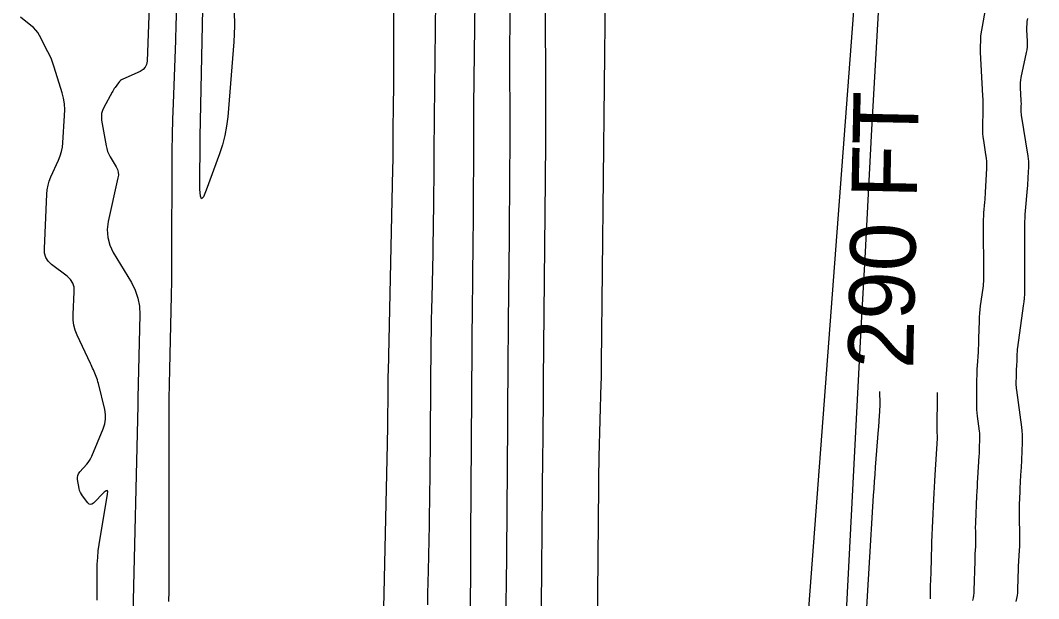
# Model space of a CAD drawing. Extents: x 1768942 to 1774819, y 723037 to 732099.
# Drawn here: x 1770462.7 to 1770556.2, y 730327.7 to 730380.8 of the extents above; entities that cross this region are included whole.
import ezdxf

# ---------------------------------------------------------------- set-up
doc = ezdxf.new("R2010")
doc.units = 0
for name, color, linetype in [('R_Contour Annot', 7, 'Continuous'), ('R_Contours', 7, 'Continuous'), ('R_Horz Alg', 7, 'Continuous')]:
    doc.layers.add(name, color=color, linetype=linetype)

msp = doc.modelspace()

# ---------------------------------------------------------------- linework, layer by layer
at = {"layer": 'R_Contours'}
for points in [[(1770503.977, 730319.774), (1770504.052, 730330.497), (1770504.054, 730330.74), (1770504.056, 730330.984), (1770504.058, 730331.227), (1770504.06, 730331.47), (1770504.07, 730332.443), (1770504.072, 730332.687), (1770504.074, 730332.93), (1770504.076, 730333.173), (1770504.078, 730333.417), (1770504.231, 730355.112), (1770504.233, 730355.433), (1770504.236, 730355.754), (1770504.238, 730356.075), (1770504.242, 730356.395), (1770504.254, 730357.679), (1770504.257, 730357.999), (1770504.26, 730358.32), (1770504.263, 730358.641), (1770504.265, 730358.962), (1770504.336, 730368.866), (1770504.338, 730369.206), (1770504.339, 730369.546), (1770504.34, 730369.887), (1770504.339, 730370.227), (1770504.337, 730371.589), (1770504.337, 730371.929), (1770504.338, 730372.27), (1770504.341, 730372.61), (1770504.345, 730372.951), (1770504.868, 730414.053)], [(1770482.351, 730381.694), (1770482.381, 730380.263), (1770482.313, 730378.826), (1770481.75, 730371.936), (1770481.65, 730371.068), (1770481.492, 730370.213), (1770481.278, 730369.371), (1770481.006, 730368.541), (1770479.784, 730365.192), (1770479.53, 730364.601), (1770479.349, 730364.421), (1770479.242, 730364.652), (1770479.207, 730365.295), (1770479.217, 730370.154), (1770479.218, 730370.269), (1770479.219, 730370.383), (1770479.222, 730370.498), (1770479.226, 730370.612), (1770479.243, 730371.07), (1770479.247, 730371.185), (1770479.25, 730371.3), (1770479.253, 730371.414), (1770479.256, 730371.529), (1770479.722, 730393.624)], [(1770474.908, 730392.045), (1770474.359, 730377.047), (1770474.31, 730376.737), (1770474.188, 730376.476), (1770473.992, 730376.265), (1770473.723, 730376.103), (1770472.13, 730375.388), (1770472.014, 730375.327), (1770471.91, 730375.253), (1770471.816, 730375.166), (1770471.733, 730375.065), (1770471.422, 730374.635), (1770471.347, 730374.526), (1770471.274, 730374.415), (1770471.205, 730374.302), (1770471.14, 730374.187), (1770470.374, 730372.785), (1770470.251, 730372.509), (1770470.177, 730372.224), (1770470.155, 730371.93), (1770470.182, 730371.629), (1770470.586, 730369.281), (1770470.644, 730369.015), (1770470.726, 730368.759), (1770470.831, 730368.51), (1770470.959, 730368.271), (1770471.519, 730367.33), (1770471.634, 730367.091), (1770471.7, 730366.844), (1770471.715, 730366.588), (1770471.681, 730366.325), (1770470.794, 730362.328), (1770470.697, 730361.584), (1770470.741, 730360.864), (1770470.927, 730360.165), (1770471.253, 730359.49), (1770472.909, 730356.721), (1770473.264, 730356.024), (1770473.512, 730355.299), (1770473.653, 730354.546), (1770473.687, 730353.765), (1770473.498, 730346.139), (1770473.497, 730346.08), (1770473.496, 730346.021), (1770473.495, 730345.962), (1770473.495, 730345.904), (1770473.496, 730345.668), (1770473.496, 730345.609), (1770473.495, 730345.551), (1770473.494, 730345.492), (1770473.493, 730345.433), (1770473.044, 730326.3)], [(1770496.949, 730392.333), (1770496.958, 730375.138), (1770496.958, 730374.624), (1770496.956, 730374.111), (1770496.953, 730373.598), (1770496.948, 730373.084), (1770496.922, 730370.578), (1770496.92, 730370.291), (1770496.917, 730370.004), (1770496.914, 730369.717), (1770496.912, 730369.43), (1770496.902, 730368.282), (1770496.899, 730367.995), (1770496.895, 730367.708), (1770496.89, 730367.421), (1770496.884, 730367.134), (1770496.465, 730348.569), (1770496.457, 730348.231), (1770496.452, 730347.893), (1770496.447, 730347.555), (1770496.443, 730347.217), (1770496.407, 730343.226), (1770496.404, 730342.898), (1770496.399, 730342.571), (1770496.394, 730342.244), (1770496.387, 730341.917), (1770495.994, 730324.087)], [(1770516.482, 730391.831), (1770516.039, 730349.31), (1770516.033, 730348.847), (1770516.025, 730348.384), (1770516.016, 730347.92), (1770516.005, 730347.457), (1770515.827, 730340.732), (1770515.811, 730340.075), (1770515.797, 730339.417), (1770515.787, 730338.759), (1770515.779, 730338.101), (1770515.435, 730301.58), (1770515.431, 730300.949), (1770515.429, 730300.318), (1770515.43, 730299.687), (1770515.433, 730299.056), (1770515.486, 730292.163), (1770515.489, 730291.645), (1770515.49, 730291.127), (1770515.488, 730290.609), (1770515.485, 730290.091), (1770515.139, 730251.536)], [(1770510.513, 730323.525), (1770510.685, 730341.012), (1770510.688, 730341.355), (1770510.691, 730341.699), (1770510.694, 730342.043), (1770510.696, 730342.387), (1770510.725, 730346.463), (1770510.727, 730346.798), (1770510.73, 730347.133), (1770510.733, 730347.469), (1770510.736, 730347.804), (1770510.917, 730366.108), (1770510.92, 730366.409), (1770510.923, 730366.71), (1770510.925, 730367.011), (1770510.927, 730367.312), (1770510.936, 730368.515), (1770510.938, 730368.816), (1770510.939, 730369.117), (1770510.94, 730369.418), (1770510.939, 730369.719), (1770510.911, 730386.799)], [(1770550.144, 730327.56), (1770550.192, 730327.788), (1770550.229, 730328.017), (1770550.253, 730328.248), (1770550.265, 730328.48), (1770550.338, 730331.152), (1770550.343, 730331.323), (1770550.35, 730331.493), (1770550.358, 730331.664), (1770550.367, 730331.834), (1770550.407, 730332.516), (1770550.415, 730332.686), (1770550.42, 730332.857), (1770550.421, 730333.027), (1770550.418, 730333.198), (1770550.4, 730333.972), (1770550.397, 730334.157), (1770550.397, 730334.343), (1770550.401, 730334.529), (1770550.407, 730334.715), (1770550.514, 730337.165), (1770550.533, 730337.57), (1770550.553, 730337.974), (1770550.576, 730338.379), (1770550.6, 730338.783), (1770550.727, 730340.834), (1770550.738, 730341.021), (1770550.748, 730341.209), (1770550.756, 730341.396), (1770550.763, 730341.584), (1770550.79, 730342.335), (1770550.793, 730342.522), (1770550.788, 730342.709), (1770550.775, 730342.896), (1770550.753, 730343.082), (1770550.565, 730344.476), (1770550.531, 730344.77), (1770550.508, 730345.065), (1770550.495, 730345.361), (1770550.493, 730345.658), (1770550.519, 730347.853), (1770550.525, 730348.166), (1770550.534, 730348.478), (1770550.549, 730348.791), (1770550.567, 730349.103), (1770550.648, 730350.351), (1770550.667, 730350.664), (1770550.682, 730350.976), (1770550.694, 730351.289), (1770550.703, 730351.601), (1770550.742, 730353.219), (1770550.755, 730353.56), (1770550.777, 730353.901), (1770550.81, 730354.241), (1770550.853, 730354.58), (1770551.083, 730356.215), (1770551.107, 730356.414), (1770551.125, 730356.614), (1770551.136, 730356.814), (1770551.14, 730357.014), (1770551.144, 730357.818), (1770551.145, 730358.018), (1770551.145, 730358.219), (1770551.144, 730358.42), (1770551.142, 730358.621), (1770551.116, 730360.939), (1770551.114, 730361.121), (1770551.114, 730361.304), (1770551.114, 730361.486), (1770551.115, 730361.669), (1770551.123, 730362.398), (1770551.127, 730362.581), (1770551.134, 730362.763), (1770551.145, 730362.945), (1770551.159, 730363.126), (1770551.246, 730364.115), (1770551.265, 730364.34), (1770551.281, 730364.566), (1770551.296, 730364.792), (1770551.308, 730365.018), (1770551.418, 730367.176), (1770551.426, 730367.502), (1770551.417, 730367.828), (1770551.39, 730368.152), (1770551.346, 730368.476), (1770551.135, 730369.769), (1770551.09, 730370.092), (1770551.061, 730370.417), (1770551.046, 730370.743), (1770551.047, 730371.069), (1770551.083, 730372.485), (1770551.089, 730372.83), (1770551.087, 730373.175), (1770551.078, 730373.52), (1770551.062, 730373.865), (1770550.833, 730377.861), (1770550.83, 730377.918), (1770550.83, 730377.975), (1770550.83, 730378.032), (1770550.832, 730378.089), (1770550.845, 730378.324), (1770550.848, 730378.377), (1770550.85, 730378.43), (1770550.853, 730378.482), (1770550.855, 730378.535), (1770550.863, 730378.745), (1770550.865, 730378.797), (1770550.866, 730378.85), (1770550.867, 730378.902), (1770550.867, 730378.954), (1770550.865, 730379.164), (1770550.866, 730379.216), (1770550.869, 730379.268), (1770550.875, 730379.32), (1770550.883, 730379.372), (1770552.026, 730385.95)], [(1770500.113, 730327.142), (1770500.128, 730328.189), (1770500.146, 730329.235), (1770500.168, 730330.281), (1770500.261, 730334.503), (1770500.282, 730335.531), (1770500.299, 730336.559), (1770500.314, 730337.587), (1770500.325, 730338.616), (1770500.439, 730351.25), (1770500.45, 730352.269), (1770500.464, 730353.287), (1770500.482, 730354.306), (1770500.503, 730355.324), (1770500.595, 730359.398), (1770500.616, 730360.416), (1770500.634, 730361.435), (1770500.648, 730362.453), (1770500.658, 730363.472), (1770500.695, 730367.688), (1770500.704, 730368.73), (1770500.713, 730369.772), (1770500.723, 730370.815), (1770500.734, 730371.857), (1770500.845, 730382.648)], [(1770476.353, 730327.451), (1770476.372, 730328.398), (1770476.386, 730329.344), (1770476.393, 730330.291), (1770476.394, 730331.238), (1770476.371, 730343.331), (1770476.373, 730344.687), (1770476.384, 730346.043), (1770476.404, 730347.399), (1770476.433, 730348.754), (1770476.567, 730354.176), (1770476.597, 730355.531), (1770476.619, 730356.887), (1770476.633, 730358.243), (1770476.64, 730359.599), (1770476.656, 730367.376), (1770476.665, 730368.823), (1770476.687, 730370.27), (1770476.721, 730371.717), (1770476.768, 730373.163), (1770476.98, 730378.948), (1770477.03, 730380.395), (1770477.074, 730381.841)], [(1770469.776, 730327.586), (1770469.77, 730330.283), (1770469.781, 730330.889), (1770469.818, 730331.492), (1770469.879, 730332.094), (1770469.966, 730332.693), (1770470.732, 730337.312), (1770470.749, 730337.543), (1770470.701, 730337.648), (1770470.588, 730337.625), (1770470.41, 730337.476), (1770469.426, 730336.482), (1770469.289, 730336.379), (1770469.158, 730336.35), (1770469.031, 730336.395), (1770468.908, 730336.514), (1770468.429, 730337.14), (1770468.319, 730337.301), (1770468.232, 730337.471), (1770468.165, 730337.651), (1770468.12, 730337.841), (1770467.979, 730338.645), (1770467.965, 730338.837), (1770467.994, 730339.018), (1770468.065, 730339.186), (1770468.178, 730339.343), (1770468.809, 730340.048), (1770468.951, 730340.22), (1770469.077, 730340.403), (1770469.187, 730340.596), (1770469.281, 730340.798), (1770470.324, 730343.314), (1770470.466, 730343.746), (1770470.536, 730344.185), (1770470.535, 730344.628), (1770470.463, 730345.078), (1770469.89, 730347.468), (1770469.848, 730347.628), (1770469.799, 730347.786), (1770469.744, 730347.942), (1770469.682, 730348.096), (1770469.422, 730348.706), (1770469.356, 730348.858), (1770469.288, 730349.01), (1770469.22, 730349.161), (1770469.149, 730349.311), (1770467.927, 730351.887), (1770467.745, 730352.343), (1770467.622, 730352.81), (1770467.559, 730353.288), (1770467.557, 730353.779), (1770467.673, 730355.863), (1770467.651, 730356.289), (1770467.533, 730356.671), (1770467.321, 730357.009), (1770467.013, 730357.304), (1770465.594, 730358.397), (1770465.286, 730358.692), (1770465.072, 730359.03), (1770464.951, 730359.413), (1770464.924, 730359.838), (1770465.148, 730364.828), (1770465.186, 730365.243), (1770465.263, 730365.647), (1770465.378, 730366.043), (1770465.532, 730366.429), (1770466.226, 730367.955), (1770466.381, 730368.341), (1770466.5, 730368.737), (1770466.582, 730369.141), (1770466.627, 730369.555), (1770466.789, 730372.053), (1770466.8, 730372.585), (1770466.763, 730373.112), (1770466.678, 730373.633), (1770466.545, 730374.149), (1770465.827, 730376.495), (1770465.707, 730376.857), (1770465.571, 730377.213), (1770465.417, 730377.563), (1770465.248, 730377.905), (1770464.468, 730379.393), (1770464.312, 730379.656), (1770464.132, 730379.899), (1770463.926, 730380.121), (1770463.695, 730380.322), (1770462.724, 730381.085)], [(1770507.642, 730381.46), (1770507.632, 730380.112), (1770507.627, 730378.765), (1770507.627, 730377.417), (1770507.638, 730371.036), (1770507.638, 730370.184), (1770507.637, 730369.332), (1770507.633, 730368.48), (1770507.628, 730367.628), (1770507.604, 730364.219), (1770507.598, 730363.367), (1770507.591, 730362.515), (1770507.583, 730361.663), (1770507.575, 730360.811), (1770507.5, 730353.188), (1770507.491, 730352.316), (1770507.484, 730351.444), (1770507.477, 730350.572), (1770507.47, 730349.7), (1770507.395, 730339.103), (1770507.389, 730338.209), (1770507.382, 730337.315), (1770507.374, 730336.421), (1770507.365, 730335.526), (1770507.298, 730328.703), (1770507.29, 730327.79), (1770507.282, 730326.877)], [(1770554.128, 730327.469), (1770554.184, 730327.731), (1770554.225, 730327.995), (1770554.253, 730328.26), (1770554.268, 730328.528), (1770554.297, 730329.601), (1770554.305, 730329.869), (1770554.315, 730330.138), (1770554.328, 730330.406), (1770554.342, 730330.674), (1770554.429, 730332.169), (1770554.446, 730332.508), (1770554.455, 730332.846), (1770554.457, 730333.185), (1770554.452, 730333.524), (1770554.411, 730335.25), (1770554.407, 730335.525), (1770554.407, 730335.8), (1770554.412, 730336.075), (1770554.422, 730336.35), (1770554.473, 730337.509), (1770554.484, 730337.754), (1770554.496, 730337.999), (1770554.51, 730338.244), (1770554.524, 730338.488), (1770554.585, 730339.468), (1770554.599, 730339.712), (1770554.612, 730339.957), (1770554.623, 730340.202), (1770554.633, 730340.447), (1770554.691, 730342.059), (1770554.696, 730342.409), (1770554.686, 730342.758), (1770554.661, 730343.107), (1770554.622, 730343.455), (1770554.166, 730346.836), (1770554.147, 730346.995), (1770554.134, 730347.155), (1770554.127, 730347.315), (1770554.126, 730347.476), (1770554.135, 730348.204), (1770554.137, 730348.322), (1770554.141, 730348.44), (1770554.146, 730348.557), (1770554.153, 730348.675), (1770554.184, 730349.145), (1770554.191, 730349.262), (1770554.196, 730349.38), (1770554.201, 730349.497), (1770554.204, 730349.615), (1770554.218, 730350.206), (1770554.224, 730350.344), (1770554.233, 730350.481), (1770554.246, 730350.618), (1770554.263, 730350.754), (1770554.802, 730354.59), (1770554.846, 730354.943), (1770554.877, 730355.298), (1770554.897, 730355.653), (1770554.905, 730356.01), (1770554.913, 730357.676), (1770554.914, 730357.913), (1770554.913, 730358.15), (1770554.912, 730358.387), (1770554.91, 730358.624), (1770554.899, 730359.572), (1770554.897, 730359.809), (1770554.897, 730360.046), (1770554.897, 730360.283), (1770554.899, 730360.52), (1770554.915, 730361.997), (1770554.922, 730362.322), (1770554.934, 730362.647), (1770554.954, 730362.971), (1770554.979, 730363.296), (1770555.161, 730365.371), (1770555.181, 730365.616), (1770555.199, 730365.862), (1770555.215, 730366.107), (1770555.229, 730366.353), (1770555.279, 730367.335), (1770555.285, 730367.58), (1770555.278, 730367.825), (1770555.258, 730368.069), (1770555.225, 730368.312), (1770554.608, 730372.096), (1770554.593, 730372.205), (1770554.583, 730372.315), (1770554.578, 730372.425), (1770554.578, 730372.536), (1770554.589, 730372.979), (1770554.591, 730373.09), (1770554.59, 730373.201), (1770554.588, 730373.311), (1770554.582, 730373.422), (1770554.514, 730374.608), (1770554.509, 730374.842), (1770554.519, 730375.075), (1770554.544, 730375.306), (1770554.585, 730375.537), (1770555.072, 730377.828), (1770555.118, 730378.085), (1770555.147, 730378.343), (1770555.16, 730378.603), (1770555.156, 730378.865), (1770555.108, 730379.913), (1770555.103, 730380.174), (1770555.112, 730380.435), (1770555.136, 730380.695), (1770555.174, 730380.954)], [(1770539.815, 730317.183), (1770541.035, 730337.183), (1770541.076, 730337.83), (1770541.12, 730338.477), (1770541.167, 730339.124), (1770541.217, 730339.77), (1770541.492, 730343.232), (1770541.508, 730343.441), (1770541.524, 730343.649), (1770541.538, 730343.858), (1770541.552, 730344.067), (1770541.606, 730344.907), (1770541.617, 730345.115), (1770541.624, 730345.322), (1770541.627, 730345.529), (1770541.626, 730345.737), (1770541.613, 730346.567), (1770541.611, 730346.736)], [(1770546.24, 730327.705), (1770546.243, 730327.998), (1770546.249, 730328.291), (1770546.256, 730328.584), (1770546.265, 730328.877), (1770546.305, 730330.08), (1770546.314, 730330.357), (1770546.322, 730330.634), (1770546.33, 730330.911), (1770546.338, 730331.188), (1770546.383, 730332.845), (1770546.384, 730332.854), (1770546.384, 730332.867), (1770546.384, 730332.886), (1770546.384, 730332.891), (1770546.556, 730336.821), (1770546.582, 730337.386), (1770546.61, 730337.95), (1770546.641, 730338.514), (1770546.675, 730339.078), (1770546.882, 730342.411), (1770546.883, 730342.436), (1770546.884, 730342.461), (1770546.885, 730342.485), (1770546.886, 730342.51), (1770546.89, 730342.61), (1770546.89, 730342.635), (1770546.89, 730342.66), (1770546.888, 730342.685), (1770546.885, 730342.71), (1770546.86, 730342.895), (1770546.856, 730342.935), (1770546.852, 730342.974), (1770546.851, 730343.013), (1770546.85, 730343.053), (1770546.892, 730346.625)]]:
    msp.add_lwpolyline(points, dxfattribs=at)
at = {"layer": 'R_Horz Alg'}
msp.add_line((1770527.746, 730229.262), (1770556.177, 730606.87), dxfattribs=at)
msp.add_arc((1781982.994, 729746.521), 11459.16, 175.6942048, 179.4795914, dxfattribs=at)

# ---------------------------------------------------------------- texts
at = {"layer": 'R_Contour Annot'}
msp.add_text('290 FT', height=6, rotation=88.79583, dxfattribs=at).set_placement((1770544.655, 730348.775))

doc.saveas('drawing.dxf')
